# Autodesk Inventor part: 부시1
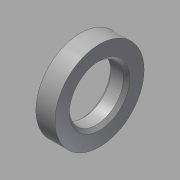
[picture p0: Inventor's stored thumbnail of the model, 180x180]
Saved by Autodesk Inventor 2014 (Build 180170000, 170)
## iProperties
Created: 2015-09
Part Number: 부시1
Material: 강철, 연강
Document SubType Name: Modeling
Designer: mduedu
Density: 7.86 g/cm^3
Description: 외주 가공
Mass: 17.8983 g
Surface Area: 15.6581 cm^2
Volume: 2.27713 cm^3
Appearance: 강철
Author: mduedu
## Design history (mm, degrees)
sketch "스케치1"
  geometry: C1 r 14 at (0, 0); C2 r 8.5 at (0, 0); 1 further point
  constraints: 2 centre point, 2 coincident
  dimensions: "d0" = 28 diameter of C1; "d2" = 17 diameter of C2
extrude "돌출1" new body sketch "스케치1" distance "d3" = 6; taper "d4" = 0 deg
chamfer "모따기1" distance "d5" = 1; stored, may be unused: second distance "d6" = 2, angle "d7" = 45 deg
node "솔리드1"
